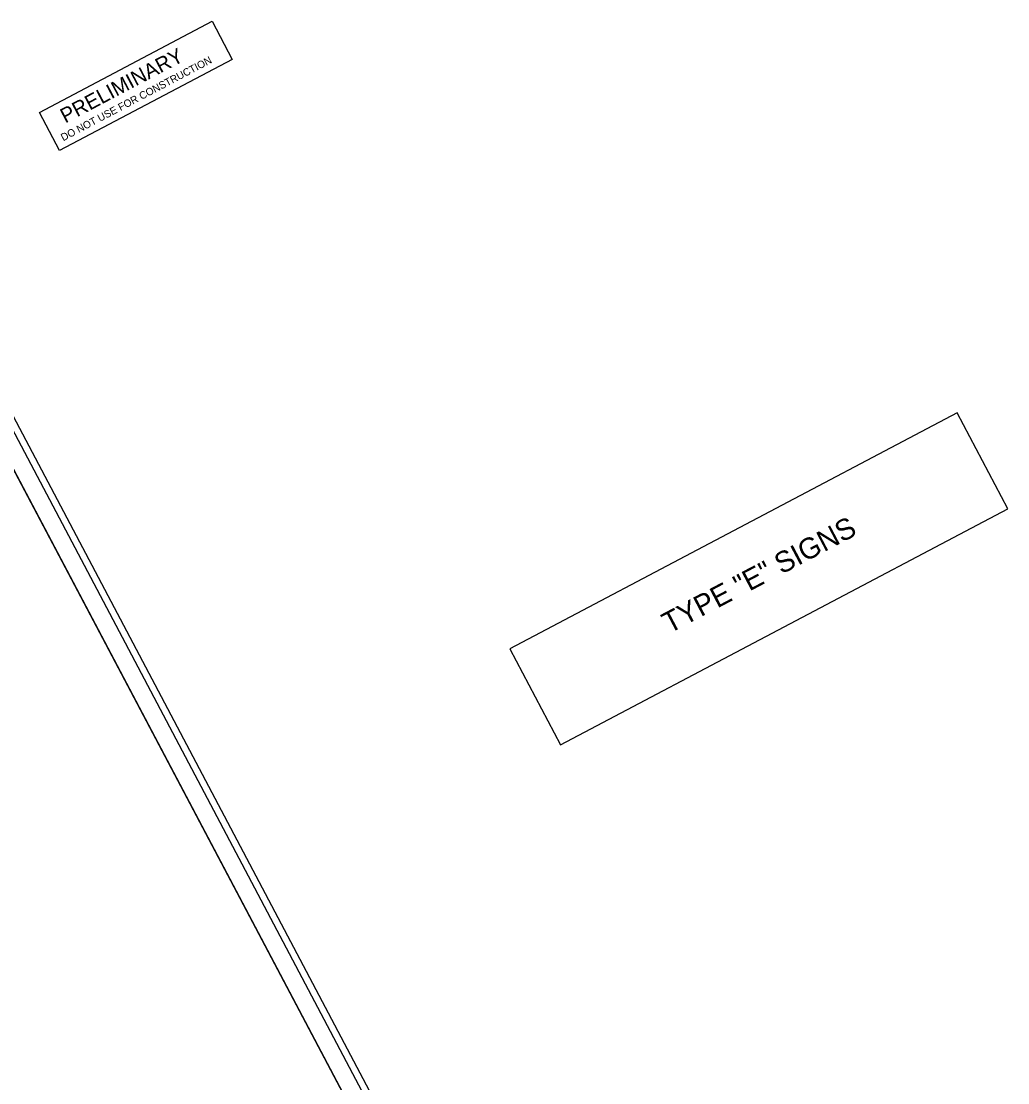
# Model space of a CAD drawing. Extents: x 1487176 to 1489663, y 497841 to 500965.
# Drawn here: x 1488976 to 1489637, y 499031 to 499743 of the extents above; entities that cross this region are included whole.
import ezdxf

# ---------------------------------------------------------------- set-up
doc = ezdxf.new("R2010")
doc.units = 0
for name, color, linetype in [('DEV TUBULAR MARKER PLAN VIEW CELL', 7, 'Continuous'), ('MARK BICYCLE SYMBOL CELL', 7, 'Continuous'), ('MARK STRAIGHT ARROW CELL', 7, 'Continuous'), ('Prop Mkg Solid White Lane Line', 7, 'Continuous'), ('Scratch_Level_1', 7, 'Continuous'), ('Scratch_Level_3', 7, 'Continuous'), ('Scratch_Level_6', 7, 'Continuous')]:
    doc.layers.add(name, color=color, linetype=linetype)

msp = doc.modelspace()

# ---------------------------------------------------------------- linework, layer by layer
at = {"layer": 'DEV TUBULAR MARKER PLAN VIEW CELL'}
msp.add_lwpolyline([(1488120.36, 498369.24), (1487949.53, 498194.25), (1487512.58, 499019.67), (1488662.1, 499625.77), (1488771.25, 499418.79), (1488936.61, 499505.98), (1489317.21, 498785.18), (1488242.69, 498217.81)], close=True, dxfattribs=at)
at = {"layer": 'MARK BICYCLE SYMBOL CELL'}
msp.add_lwpolyline([(1488987.73, 499681.7), (1489103.58, 499742.87), (1489117.08, 499717.3), (1489001.23, 499656.13)], close=True, dxfattribs=at)
at = {"layer": 'MARK STRAIGHT ARROW CELL'}
msp.add_lwpolyline([(1488830.57, 499741.98), (1487342.38, 498956.18), (1487854.09, 497987.08), (1489342.28, 498772.88)], close=True, dxfattribs=at)
at = {"layer": 'Prop Mkg Solid White Lane Line'}
for points in [[(1488826.93, 499713.69), (1487500.49, 499013.3), (1487990.76, 498084.79), (1489317.21, 498785.18)], [(1489337.27, 499257.47), (1489637.17, 499415.82), (1489603.16, 499480.25), (1489303.26, 499321.89)]]:
    msp.add_lwpolyline(points, close=True, dxfattribs=at)
at = {"layer": 'Scratch_Level_1'}
msp.add_lwpolyline([(1488835.94, 499722.2), (1487363.2, 498944.56), (1487856.23, 498010.83), (1489328.96, 498788.47)], close=True, dxfattribs=at)
at = {"layer": 'Scratch_Level_3'}
msp.add_lwpolyline([(1488987.73, 499681.7), (1489103.58, 499742.87), (1489117.08, 499717.3), (1489001.23, 499656.13)], close=True, dxfattribs=at)
msp.add_lwpolyline([(1488987.73, 499681.7), (1489103.58, 499742.87), (1489117.08, 499717.3), (1489001.23, 499656.13)], close=True, dxfattribs=at)

# ---------------------------------------------------------------- texts
for s, height, p in [(' PRELIMINARY', 9.9999, (1489001.81, 499672.44)), ('DO NOT USE FOR CONSTRUCTION', 5.0001, (1489003.72, 499662.29))]:
    msp.add_text(s, height=height, rotation=27.83509, dxfattribs=at).set_placement(p)
at = {"layer": 'Scratch_Level_6'}
msp.add_text('TYPE "E" SIGNS', height=14, rotation=27.83425, dxfattribs=at).set_placement((1489410.16, 499331.89))

doc.saveas('drawing.dxf')
